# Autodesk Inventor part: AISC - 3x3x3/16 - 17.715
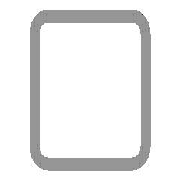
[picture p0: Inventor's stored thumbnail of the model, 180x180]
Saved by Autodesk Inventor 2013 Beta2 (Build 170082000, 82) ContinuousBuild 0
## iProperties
IsCustomPart: 1
Created: 2010-11
Part Number: AISC - 3x3x3/16 - 17.715
Material: Steel, Mild
Description: Tube
Document SubType Name: Modeling
Standard: ANSI
Designer: Beta-8540w
Standards Organization: ANSI
Language: en-US
Size Designation: 3x3x3/16
Categories: <MemberInstance><Categories><Category DisplayName="Structural Shapes" InternalName="089c4875-fa83-4c05-b084-43b9cc11f5ed" Mnemonic="GRDR"><CategoryParameter Dis
Stock Number: 3x3x3/16
Density: 7.86 g/cm^3
_CCFamilyMember: 9
_CCFamilyDisplayName: ANSI AISC (Square) - Tube
_FrameMemberDoc: Frame Member File
_Version: 15.0.0
_GetPNFromCC: 1
G_L: 17.715 in
G_W: 3.000 in
G_H: 3.000 in
Author: Beta-8540w
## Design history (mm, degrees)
node "Start plane"
node "End plane"
sketch "Sketch"
  geometry: L1 (-38.1, -28.575)-(-38.1, 28.575); L2 (-28.575, 38.1)-(28.575, 38.1); L3 (38.1, 28.575)-(38.1, -28.575); L4 (28.575, -38.1)-(-28.575, -38.1); L5 (-28.575, 33.337)-(28.575, 33.338); L6 (33.338, 28.575)-(33.338, -28.575); L7 (28.575, -33.337)-(-28.575, -33.338); L8 (-33.338, -28.575)-(-33.338, 28.575); L9 (0, 56.102)-(0, -56.102) reference; L10 (-56.102, 0)-(56.102, 0) reference; A1 r 9.525 centre (-28.575, -28.575) between (-38.1, -28.575) and (-28.575, -38.1); A2 r 9.525 centre (-28.575, 28.575) between (-28.575, 38.1) and (-38.1, 28.575); A3 r 9.525 centre (28.575, 28.575) between (38.1, 28.575) and (28.575, 38.1); A4 r 9.525 centre (28.575, -28.575) between (28.575, -38.1) and (38.1, -28.575); A5 r 4.763 centre (-28.575, 28.575) between (-28.575, 33.337) and (-33.338, 28.575); A6 r 4.763 centre (28.575, 28.575) between (33.338, 28.575) and (28.575, 33.338); A7 r 4.763 centre (28.575, -28.575) between (28.575, -33.337) and (33.338, -28.575); A8 r 4.763 centre (-28.575, -28.575) between (-33.338, -28.575) and (-28.575, -33.338)
  constraints: 16 end point, 16 point on circle, 8 centre point, 8 tangent, 4 parallel, 3 equal radius, 2 perpendicular, 7 other
  dimensions: "d10" = 76.2 distance between parallel lines of L2 L4 (= G_H); "d11" = 76.2 distance between parallel lines of L1 L3 (= G_W); "d12" = 4.7625 distance between parallel lines of L3 L6 (= G_T); "d15" = 38.1 distance between parallel lines of L2 L10 (= 0.5 x d10); "d16" = 38.1 distance between parallel lines of L9 L3 (= 0.5 x d11); "d17" = 9.525 radius of A1 (= G_IR)
extrude "Body" new body sketch "Sketch" stored distance "d3" = 449.97309 (= G_L); taper "d4" = 0 deg
node "Driven Length"
  sketch "Sketch3"
    geometry: L1 (0, 0)-(10, 0) reference
    constraints: 2 end point, 1 horizontal
  workplane "Work Plane3"
  sketch "Sketch4"
    geometry: L1 (-2, 0)-(12, 0) reference; L2 (-2, 449.973)-(12, 449.973) reference
    dimensions: "d19" = 449.97309 distance between parallel lines of L1 L2 (derived)
body "Solid1"
other parameters: "G_W" = 76.2 [user parameter; used in 1 equation term], "G_H" = 76.2 [user parameter; used in 1 equation term], "G_T" = 4.7625 [user parameter; used in 1 equation term], "G_IR" = 9.525 [user parameter; used in 1 equation term], "G_L" = 449.97309 (= d19) [user parameter; used in 1 equation term], "G_OFFSET_START" = 0 [user parameter; used in 1 equation term], "G_OFFSET_END" = 0 [user parameter; used in 1 equation term], "d13" = 0 (computed from G_OFFSET_START), "d14" = 449.97309 (= G_OFFSET_END + B_L), "B_L" = 449.97309 [user parameter; used in 1 equation term], "d18" = 90 deg
